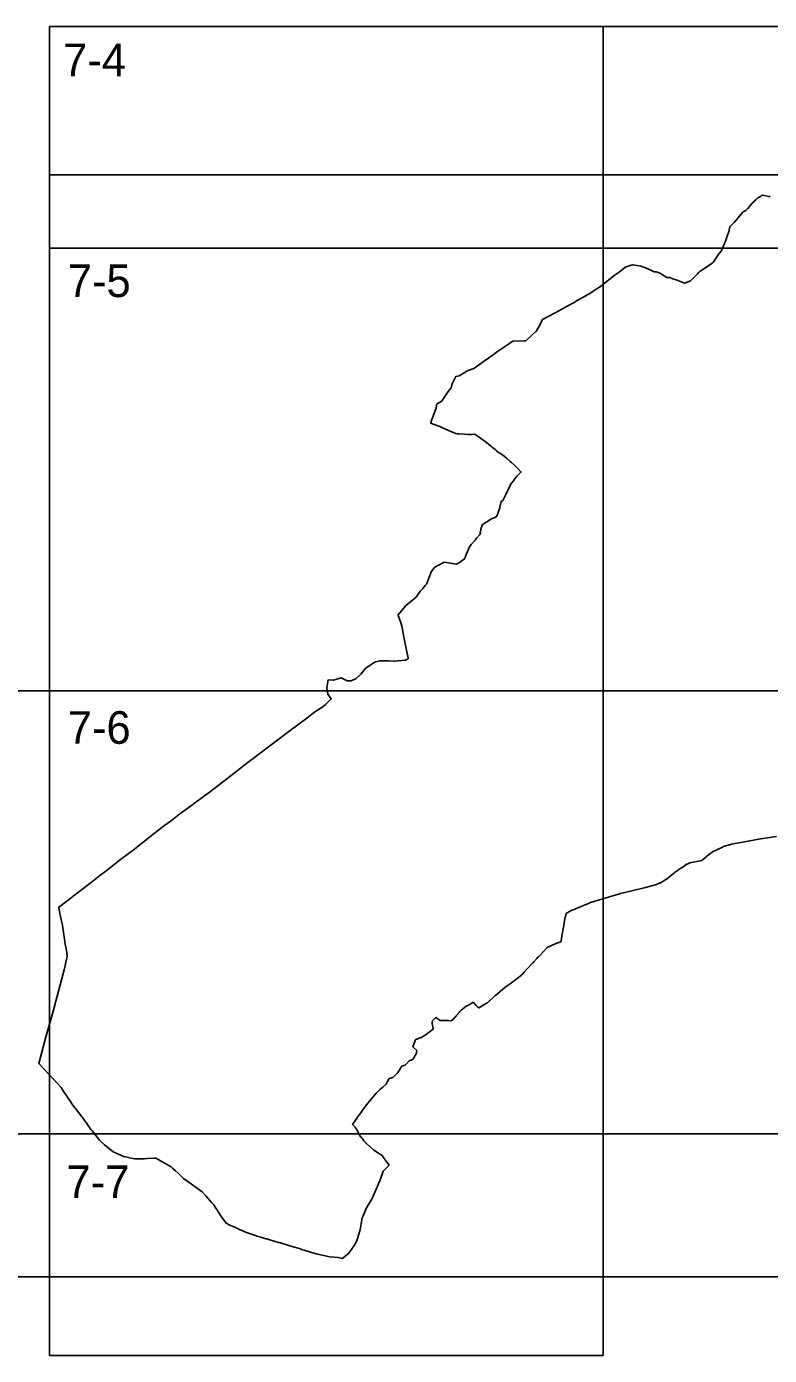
# Model space of a CAD drawing. Extents: x -449577 to -425530, y -1150048 to -1121091.
# Drawn here: x -440104.8 to -439895.1, y -1126653.4 to -1126278.4 of the extents above; entities that cross this region are included whole.
import ezdxf

# ---------------------------------------------------------------- set-up
doc = ezdxf.new("R2010")
doc.units = 0
for name, color, linetype in [('Vrstva 1', 7, 'Continuous'), ('Vrstva 10', 7, 'Continuous'), ('Vrstva 4', 7, 'Continuous')]:
    doc.layers.add(name, color=color, linetype=linetype)

msp = doc.modelspace()

# ---------------------------------------------------------------- linework, layer by layer
at = {"layer": 'Vrstva 1'}
for points in [[(-439894.95, -1126326.41), (-439895.41, -1126326.32), (-439897, -1126326), (-439897.3, -1126326.11), (-439897.86, -1126326.46), (-439898.41, -1126326.78), (-439898.9, -1126327.24), (-439899.43, -1126327.73), (-439899.83, -1126328.12), (-439899.84, -1126328.13), (-439900.17, -1126328.47), (-439900.3, -1126328.61), (-439900.81, -1126329.16), (-439901.26, -1126329.71), (-439901.42, -1126329.9), (-439901.78, -1126330.33), (-439902.52, -1126330.66), (-439902.54, -1126330.66), (-439902.74, -1126330.91), (-439903.6, -1126331.93), (-439903.98, -1126332.38), (-439905.11, -1126333.74), (-439905.12, -1126333.75), (-439906.36, -1126334.92), (-439906.48, -1126335.76), (-439906.53, -1126336.13), (-439906.57, -1126336.23), (-439907.05, -1126337.58), (-439907.49, -1126338.82), (-439907.52, -1126338.9), (-439907.82, -1126339.59), (-439908.75, -1126341.77), (-439908.77, -1126341.78), (-439909.34, -1126342.46), (-439909.64, -1126342.81), (-439909.64, -1126342.82), (-439909.98, -1126343.36), (-439910.85, -1126344.75), (-439910.94, -1126344.89), (-439911.11, -1126345.02), (-439911.64, -1126345.41), (-439912.25, -1126345.86), (-439912.25, -1126345.86), (-439913.22, -1126346.49), (-439913.35, -1126346.58), (-439913.53, -1126346.7), (-439914.83, -1126347.56), (-439914.84, -1126347.57), (-439915.1, -1126347.83), (-439915.22, -1126347.95), (-439915.44, -1126348.18), (-439915.72, -1126348.46), (-439916.29, -1126349.03), (-439917.45, -1126350.19), (-439917.65, -1126350.27), (-439919.15, -1126350.84), (-439921.96, -1126349.72), (-439921.96, -1126349.73), (-439921.97, -1126349.75), (-439922.88, -1126349.37), (-439923.19, -1126349.24), (-439923.21, -1126349.24), (-439923.6, -1126349.24), (-439924.08, -1126349.24), (-439925.64, -1126348.25), (-439925.9, -1126348.12), (-439926.19, -1126347.96), (-439926.25, -1126347.93), (-439926.29, -1126347.91), (-439926.83, -1126347.68), (-439926.88, -1126347.68), (-439926.89, -1126347.68), (-439927.04, -1126347.67), (-439927.16, -1126347.66), (-439927.47, -1126347.64), (-439927.49, -1126347.64), (-439927.49, -1126347.64), (-439927.6, -1126347.6), (-439927.84, -1126347.5), (-439928.44, -1126347.25), (-439928.6, -1126347.18), (-439930.12, -1126346.45), (-439930.74, -1126346.27), (-439931.41, -1126346.07), (-439933.73, -1126345.64), (-439933.74, -1126345.64), (-439934.14, -1126345.75), (-439935.88, -1126346.33), (-439936.01, -1126346.44), (-439937.22, -1126347.4), (-439937.22, -1126347.4), (-439938.37, -1126348.27), (-439938.94, -1126348.7), (-439939.52, -1126349.14), (-439939.68, -1126349.26), (-439941.81, -1126350.9), (-439942.88, -1126351.72), (-439943.35, -1126352.06), (-439944.11, -1126352.57), (-439944.36, -1126352.73), (-439944.95, -1126353.12), (-439944.99, -1126353.15), (-439945.2, -1126353.29), (-439946.11, -1126353.89), (-439946.12, -1126353.89), (-439946.59, -1126354.15), (-439946.74, -1126354.23), (-439946.92, -1126354.33), (-439947.38, -1126354.58), (-439947.56, -1126354.69), (-439947.72, -1126354.78), (-439947.82, -1126354.84), (-439948.06, -1126354.98), (-439949.72, -1126355.92), (-439949.89, -1126356.01), (-439950.12, -1126356.14), (-439952.59, -1126357.54), (-439952.71, -1126357.61), (-439954.82, -1126358.74), (-439955.84, -1126359.29), (-439959.18, -1126361.1), (-439959.35, -1126361.4), (-439959.41, -1126361.51), (-439960.19, -1126362.97), (-439960.87, -1126364.29), (-439961.01, -1126364.42), (-439961.1, -1126364.5), (-439962.24, -1126365.54), (-439963.75, -1126366.92), (-439963.92, -1126367.07), (-439963.92, -1126367.08), (-439964.39, -1126367.09), (-439967.58, -1126367.18), (-439967.59, -1126367.18), (-439968.02, -1126367.47), (-439968.85, -1126368.04), (-439971.32, -1126369.7), (-439971.36, -1126369.72), (-439971.6, -1126369.9), (-439971.87, -1126370.1), (-439974.85, -1126372.23), (-439974.92, -1126372.28), (-439977.92, -1126374.46), (-439978.39, -1126374.8), (-439978.55, -1126374.86), (-439980.49, -1126375.58), (-439980.5, -1126375.58), (-439980.89, -1126375.82), (-439982.77, -1126376.98), (-439983.69, -1126377.19), (-439983.94, -1126377.7), (-439984.7, -1126379.21), (-439984.71, -1126379.22), (-439984.78, -1126379.48), (-439984.98, -1126380.32), (-439985.81, -1126381.43), (-439987.18, -1126383.38), (-439987.74, -1126384.19), (-439987.77, -1126384.21), (-439988.93, -1126384.85), (-439989.03, -1126384.91), (-439989.1, -1126385.3), (-439989.25, -1126386.11), (-439989.3, -1126386.3), (-439990.59, -1126389.88), (-439990.76, -1126390.36), (-439990.73, -1126390.35), (-439990.71, -1126390.34), (-439990.03, -1126390.6), (-439988.22, -1126391.26), (-439987.6, -1126391.55), (-439985.31, -1126392.63), (-439985.29, -1126392.63), (-439984.13, -1126393.1), (-439983.66, -1126393.28), (-439983.63, -1126393.29), (-439983.2, -1126393.32), (-439983.06, -1126393.33), (-439982.84, -1126393.35), (-439981.24, -1126393.45), (-439980.2, -1126393.52), (-439979.15, -1126393.49), (-439978.31, -1126393.46), (-439978.3, -1126393.46), (-439978.02, -1126393.61), (-439977.65, -1126393.87), (-439977.1, -1126394.25), (-439976.71, -1126394.53), (-439975.15, -1126395.67), (-439974.98, -1126395.79), (-439973.87, -1126396.71), (-439973.48, -1126397.03), (-439973.3, -1126397.18), (-439972.55, -1126397.79), (-439972.28, -1126398.02), (-439971.68, -1126398.51), (-439971.46, -1126398.69), (-439970.82, -1126399.11), (-439970.07, -1126399.61), (-439970.04, -1126399.63), (-439969.28, -1126400.31), (-439968.4, -1126401.09), (-439967.96, -1126401.47), (-439966.95, -1126402.36), (-439966.69, -1126402.59), (-439966.64, -1126402.64), (-439966.54, -1126402.74), (-439966.53, -1126402.75), (-439966.44, -1126402.85), (-439966.41, -1126402.88), (-439965.36, -1126404.11), (-439965.37, -1126404.12), (-439965.81, -1126404.61), (-439965.87, -1126404.68), (-439966.44, -1126405.31), (-439967.26, -1126406.37), (-439967.43, -1126406.58), (-439967.99, -1126407.3), (-439968.29, -1126407.83), (-439968.31, -1126407.87), (-439968.32, -1126407.89), (-439968.45, -1126408.17), (-439969.25, -1126409.84), (-439969.56, -1126410.48), (-439970.18, -1126411.77), (-439970.29, -1126412.01), (-439970.3, -1126412.01), (-439970.34, -1126412.04), (-439970.63, -1126412.24), (-439970.71, -1126412.28), (-439970.76, -1126412.38), (-439970.85, -1126412.58), (-439970.94, -1126412.86), (-439971.11, -1126413.42), (-439971.12, -1126413.44), (-439971.24, -1126413.94), (-439971.26, -1126414.01), (-439971.25, -1126414.07), (-439971.24, -1126414.15), (-439971.24, -1126414.22), (-439971.25, -1126414.27), (-439972.13, -1126416.6), (-439972.15, -1126416.65), (-439972.17, -1126416.69), (-439972.18, -1126416.7), (-439972.88, -1126417), (-439973.13, -1126417.11), (-439973.6, -1126417.35), (-439976.21, -1126419.04), (-439976.21, -1126419.04), (-439976.58, -1126420.35), (-439976.66, -1126420.61), (-439976.77, -1126421.03), (-439976.83, -1126421.24), (-439976.83, -1126421.25), (-439976.82, -1126421.25), (-439976.65, -1126421.41), (-439976.66, -1126421.42), (-439977.02, -1126421.81), (-439977.82, -1126422.81), (-439977.83, -1126422.82), (-439978.04, -1126423.07), (-439978.04, -1126423.08), (-439978.16, -1126423.23), (-439979.32, -1126424.58), (-439979.86, -1126425.21), (-439980.62, -1126427.16), (-439981, -1126428.18), (-439981.13, -1126428.53), (-439982.66, -1126429.63), (-439983.28, -1126430.07), (-439983.46, -1126430.11), (-439983.48, -1126430.11), (-439984.11, -1126430.02), (-439986.95, -1126429.6), (-439987.44, -1126429.84), (-439988.77, -1126430.48), (-439989.31, -1126430.74), (-439989.34, -1126430.77), (-439989.77, -1126431.18), (-439989.94, -1126431.4), (-439990.6, -1126432.25), (-439990.6, -1126432.26), (-439991.27, -1126434.06), (-439991.84, -1126435.56), (-439991.84, -1126435.56), (-439991.98, -1126435.78), (-439992.31, -1126436.15), (-439993.03, -1126436.95), (-439993.73, -1126437.72), (-439993.74, -1126437.74), (-439993.87, -1126437.93), (-439994.94, -1126439.5), (-439995.41, -1126439.88), (-439996.98, -1126441.14), (-439997.65, -1126441.68), (-439997.75, -1126441.76), (-439997.78, -1126441.8), (-439998.9, -1126443.23), (-440000.04, -1126444.54), (-439999.89, -1126444.71), (-439999.88, -1126444.74), (-439999.88, -1126444.75), (-439998.87, -1126447.51), (-439998.59, -1126449.17), (-439998.27, -1126451.12), (-439997.86, -1126453.08), (-439997.13, -1126456.58), (-439997.09, -1126456.78), (-439997.74, -1126457.12), (-439997.86, -1126457.19), (-440001.03, -1126457.45), (-440001.19, -1126457.45), (-440002.68, -1126457.42), (-440005.07, -1126457.4), (-440006.35, -1126457.67), (-440006.95, -1126457.94), (-440007.93, -1126458.74), (-440009.23, -1126459.61), (-440009.32, -1126459.72), (-440010.48, -1126461.14), (-440011.93, -1126462.48), (-440012.62, -1126462.8), (-440013.22, -1126463.08), (-440014.39, -1126463.01), (-440016, -1126462.16), (-440018.24, -1126462.83), (-440019.72, -1126462.8), (-440020.1, -1126464.91), (-440020.11, -1126464.93), (-440020.12, -1126465.02), (-440019.83, -1126466.83), (-440018.86, -1126468.15), (-440018.85, -1126468.17), (-440019.59, -1126468.92), (-440020.2, -1126469.48), (-440020.45, -1126469.71), (-440021.25, -1126470.34), (-440023.18, -1126471.57), (-440023.24, -1126471.61), (-440025.21, -1126473.14), (-440025.27, -1126473.18), (-440025.76, -1126473.56), (-440030.42, -1126477.02), (-440030.45, -1126477.05), (-440035.4, -1126480.81), (-440039.66, -1126484.06), (-440040.54, -1126484.72), (-440043.11, -1126486.66), (-440047.11, -1126489.79), (-440049.55, -1126491.66), (-440052.86, -1126494.19), (-440052.91, -1126494.23), (-440057.7, -1126497.74), (-440057.93, -1126497.92), (-440061.54, -1126500.6), (-440063.93, -1126502.42), (-440065.9, -1126503.9), (-440068.22, -1126505.65), (-440068.45, -1126505.82), (-440069.58, -1126506.71), (-440074.4, -1126510.51), (-440078.29, -1126513.46), (-440082.51, -1126516.71), (-440083.8, -1126517.71), (-440086.19, -1126519.59), (-440087.37, -1126520.51), (-440091.31, -1126523.56), (-440092.24, -1126524.27), (-440093.48, -1126525.23), (-440095.8, -1126527.03), (-440095.8, -1126527.03), (-440095.76, -1126527.21), (-440095.47, -1126528.59), (-440095.44, -1126528.75), (-440094.91, -1126531.29), (-440094.75, -1126532.02), (-440094.75, -1126532.06), (-440093.82, -1126537.94), (-440093.81, -1126537.97), (-440093.51, -1126539.7), (-440093.51, -1126539.72), (-440093.45, -1126540.09), (-440093.39, -1126540.51), (-440093.42, -1126540.88), (-440093.57, -1126541.61), (-440093.95, -1126543.4), (-440094.24, -1126544.58), (-440094.26, -1126544.63), (-440095.37, -1126548.8), (-440097.47, -1126556.68), (-440099.46, -1126563.9), (-440101.39, -1126571), (-440101.4, -1126571.04), (-440096.12, -1126576.64), (-440095.07, -1126577.77), (-440094.31, -1126578.99), (-440092.29, -1126582.05), (-440092.24, -1126582.12), (-440091.23, -1126583.53), (-440091.07, -1126583.74), (-440089.19, -1126586.22), (-440088.62, -1126586.96), (-440088.59, -1126587), (-440088.07, -1126587.72), (-440086.69, -1126589.62), (-440086.36, -1126590.07), (-440084.21, -1126592.79), (-440082.81, -1126594.01), (-440080.41, -1126595.99), (-440078.67, -1126596.74), (-440077.48, -1126597.26), (-440077.35, -1126597.31), (-440076.02, -1126597.59), (-440075.88, -1126597.62), (-440074.26, -1126597.95), (-440074.23, -1126597.95), (-440073.27, -1126597.93), (-440072.89, -1126597.93), (-440072.37, -1126597.92), (-440071.69, -1126597.91), (-440070.78, -1126597.87), (-440068.83, -1126597.71), (-440068.38, -1126597.78), (-440067.72, -1126598.13), (-440066, -1126599.08), (-440064.04, -1126600.18), (-440063.52, -1126600.66), (-440062.8, -1126601.34), (-440062, -1126602.09), (-440060.68, -1126603.39), (-440060.54, -1126603.49), (-440059.35, -1126604.34), (-440056.94, -1126606.05), (-440055.3, -1126607.23), (-440054.25, -1126608.41), (-440052.61, -1126610.23), (-440051.97, -1126610.94), (-440051.61, -1126611.53), (-440051.15, -1126612.27), (-440050.21, -1126613.74), (-440049.58, -1126614.66), (-440048.54, -1126616.1), (-440047.47, -1126616.61), (-440046.09, -1126617.26), (-440044.78, -1126617.87), (-440042.81, -1126618.76), (-440041.68, -1126619.11), (-440039.96, -1126619.68), (-440039.81, -1126619.73), (-440038.72, -1126620.05), (-440037.3, -1126620.47), (-440037.29, -1126620.47), (-440037.08, -1126620.53), (-440037.02, -1126620.55), (-440036.16, -1126620.81), (-440033.77, -1126621.5), (-440033.65, -1126621.54), (-440033.17, -1126621.68), (-440030.24, -1126622.55), (-440027.55, -1126623.38), (-440027.21, -1126623.48), (-440026.45, -1126623.71), (-440024.44, -1126624.33), (-440022.71, -1126624.88), (-440019.25, -1126625.62)], [(-440019.25, -1126625.62), (-440016.86, -1126625.81), (-440015.66, -1126626.04), (-440015.55, -1126625.95), (-440013.97, -1126624.68), (-440012.94, -1126623.2), (-440012.83, -1126623.05), (-440012.31, -1126622.29), (-440012.2, -1126622.12), (-440012.06, -1126621.89), (-440011.68, -1126621.26), (-440011.41, -1126620.43), (-440011.39, -1126620.36), (-440011.37, -1126620.31), (-440011.34, -1126620.2), (-440011.31, -1126620.11), (-440011.31, -1126620.1), (-440010.68, -1126617.9), (-440010.54, -1126617.38), (-440010.09, -1126614.63), (-440010.09, -1126614.63), (-440009.9, -1126614.19), (-440009.64, -1126613.57), (-440008.85, -1126611.74), (-440007.28, -1126609.09), (-440005.53, -1126604.96), (-440005.21, -1126604.32), (-440005.17, -1126604.19), (-440004.78, -1126603.09), (-440004.19, -1126601.42), (-440002.51, -1126599.71), (-440003.44, -1126598.47), (-440003.5, -1126598.38), (-440003.55, -1126598.32), (-440003.58, -1126598.28), (-440003.65, -1126598.18), (-440003.7, -1126598.1), (-440003.78, -1126597.98), (-440004.14, -1126597.46), (-440004.51, -1126597), (-440005.08, -1126596.63), (-440005.18, -1126596.57), (-440006.83, -1126595.5), (-440009.02, -1126593.56), (-440009.15, -1126593.39), (-440009.18, -1126593.35), (-440009.26, -1126593.25), (-440009.6, -1126592.83), (-440009.93, -1126592.42), (-440010.19, -1126592.1), (-440010.67, -1126591.51), (-440010.75, -1126591.41), (-440011.25, -1126590.45), (-440011.54, -1126589.89), (-440011.77, -1126589.46), (-440011.82, -1126589.37), (-440011.86, -1126589.32), (-440012.12, -1126589.03), (-440012.32, -1126588.8), (-440012.58, -1126588.51), (-440012.8, -1126588.26), (-440010.94, -1126585.52), (-440010.85, -1126585.4), (-440010.53, -1126584.95), (-440010.21, -1126584.51), (-440008.88, -1126582.68), (-440006.2, -1126579.42), (-440005.85, -1126579.1), (-440005.14, -1126578.4), (-440005.03, -1126578.31), (-440004.84, -1126578.17), (-440004.24, -1126577.69), (-440003.38, -1126576.85), (-440002.97, -1126576.09), (-440002.5, -1126575.22), (-440001.45, -1126574.98), (-440000.05, -1126573.55), (-439999.51, -1126572.7), (-439999.5, -1126572.69), (-439999.5, -1126572.67), (-439999.29, -1126572.34), (-439999.24, -1126572.26), (-439999, -1126571.87), (-439997.84, -1126571.43), (-439996.82, -1126570.25), (-439996.29, -1126570.05), (-439996.17, -1126570), (-439995.75, -1126569.84), (-439995.53, -1126569.45), (-439995.48, -1126569.36), (-439995.31, -1126569.06), (-439994.9, -1126568.32), (-439994.7, -1126567.41), (-439994.7, -1126567.39), (-439994.69, -1126567.38), (-439995.74, -1126566.39), (-439995.76, -1126566.38), (-439995.77, -1126566.36), (-439995.82, -1126566.32), (-439995.17, -1126564.52), (-439995.1, -1126564.32), (-439994.94, -1126564.26), (-439994.21, -1126563.97), (-439993.52, -1126563.7), (-439993.4, -1126563.65), (-439992.19, -1126562.94), (-439992.07, -1126562.86), (-439992.07, -1126562.86), (-439992.06, -1126562.85), (-439991.94, -1126562.78), (-439990.08, -1126561.38), (-439990.08, -1126561.34), (-439990.11, -1126561.18), (-439990.18, -1126560.7), (-439990.24, -1126560.35), (-439990.34, -1126559.73), (-439990.36, -1126559.62), (-439990.38, -1126559.49), (-439990.4, -1126559.32), (-439990.43, -1126559.18), (-439989.89, -1126558.62), (-439989.33, -1126558.05), (-439989.29, -1126558), (-439989.15, -1126558.1), (-439988.15, -1126558.89), (-439987.47, -1126558.9), (-439987.41, -1126558.9), (-439987.16, -1126558.91), (-439987, -1126558.91), (-439985.69, -1126558.93), (-439985.06, -1126558.95), (-439984.79, -1126558.79), (-439984.76, -1126558.77), (-439984.64, -1126558.7), (-439984.5, -1126558.61), (-439984.46, -1126558.58), (-439983.92, -1126557.98), (-439983.81, -1126557.86), (-439983.72, -1126557.76), (-439983.55, -1126557.58), (-439983.47, -1126557.49), (-439983.36, -1126557.37), (-439983.33, -1126557.33), (-439983.3, -1126557.3), (-439983.25, -1126557.24), (-439983.16, -1126557.13), (-439982.76, -1126556.63), (-439982.55, -1126556.37), (-439982.3, -1126556.05), (-439982.19, -1126555.97), (-439980.73, -1126554.9), (-439980.52, -1126554.77), (-439979.16, -1126554), (-439978.76, -1126553.77), (-439978.76, -1126553.77), (-439978.62, -1126553.92), (-439977.91, -1126554.63), (-439977.54, -1126555.01), (-439977.36, -1126555.18), (-439977.21, -1126555.33), (-439977.12, -1126555.29), (-439975.84, -1126554.52), (-439975.75, -1126554.47), (-439974.82, -1126553.91), (-439974.78, -1126553.88), (-439974.45, -1126553.59), (-439974.4, -1126553.55), (-439974.23, -1126553.4), (-439974.22, -1126553.39), (-439974.22, -1126553.39), (-439974.18, -1126553.35), (-439974.14, -1126553.31), (-439973.25, -1126552.5), (-439973.23, -1126552.49), (-439972.64, -1126551.95), (-439972.53, -1126551.86), (-439972.42, -1126551.76), (-439972.42, -1126551.76), (-439972.41, -1126551.76), (-439972.41, -1126551.76), (-439972.41, -1126551.75), (-439972.4, -1126551.75), (-439972.39, -1126551.74), (-439972.39, -1126551.74), (-439972.38, -1126551.73), (-439972.38, -1126551.73), (-439972.37, -1126551.73), (-439972.37, -1126551.73), (-439971.79, -1126551.24), (-439969.8, -1126549.56), (-439968.6, -1126548.71), (-439968.48, -1126548.63), (-439968.43, -1126548.59), (-439968.41, -1126548.58), (-439968.36, -1126548.55), (-439968, -1126548.28), (-439966.76, -1126547.34), (-439966.58, -1126547.2), (-439966.37, -1126547.04), (-439966.35, -1126547.02), (-439965.47, -1126546.35), (-439965.12, -1126546.08), (-439965.07, -1126546.02), (-439964.98, -1126545.92), (-439964.34, -1126545.24), (-439963.44, -1126544.26), (-439962.08, -1126542.85), (-439961.86, -1126542.62), (-439961.61, -1126542.34), (-439960.77, -1126541.39), (-439960.48, -1126541.07), (-439960.28, -1126540.86), (-439959.99, -1126540.54), (-439958.81, -1126539.35), (-439957.88, -1126538.33), (-439955.82, -1126537.32), (-439955.66, -1126537.27), (-439955.46, -1126537.19), (-439954.02, -1126536.7), (-439953.87, -1126535.83), (-439953.71, -1126534.96), (-439953.29, -1126532.59), (-439953.21, -1126532.12), (-439952.88, -1126530.24), (-439952.68, -1126529.36), (-439952.65, -1126529.24), (-439952.6, -1126529.05), (-439952.59, -1126529.01), (-439952.57, -1126528.94), (-439952.56, -1126528.9), (-439952.55, -1126528.85), (-439952.54, -1126528.81), (-439952.53, -1126528.79), (-439952.47, -1126528.58), (-439951.39, -1126528.04), (-439951.1, -1126527.9), (-439951.08, -1126527.89), (-439950.83, -1126527.76), (-439950.78, -1126527.74), (-439949.01, -1126527.02), (-439948.98, -1126527.01), (-439948.95, -1126526.99), (-439948.15, -1126526.68), (-439947.19, -1126526.28), (-439946.38, -1126525.94), (-439945.44, -1126525.55), (-439945.36, -1126525.52), (-439944.75, -1126525.28), (-439944.9, -1126525.44), (-439944.66, -1126525.35), (-439944.17, -1126525.15), (-439943.64, -1126524.99), (-439941.94, -1126524.47), (-439941.35, -1126524.3), (-439940.9, -1126524.18), (-439940.01, -1126523.93), (-439938.7, -1126523.55), (-439937.16, -1126523.09), (-439933.62, -1126522.22), (-439930.85, -1126521.55), (-439930.18, -1126521.34), (-439928.69, -1126520.98), (-439928.48, -1126520.92), (-439927.05, -1126520.53), (-439926.45, -1126520.27), (-439926.23, -1126520.17), (-439926.07, -1126520.11), (-439925.25, -1126519.66), (-439925.19, -1126519.62), (-439923.88, -1126518.84), (-439922.73, -1126517.79), (-439922.08, -1126517.29), (-439921.95, -1126517.18), (-439921.93, -1126517.17), (-439921.77, -1126517.04), (-439921.62, -1126516.94), (-439920.82, -1126516.38), (-439920.76, -1126516.34), (-439920.69, -1126516.29), (-439920.18, -1126515.94), (-439919.81, -1126515.68), (-439919.15, -1126515.22), (-439918.56, -1126514.81), (-439918.4, -1126514.84), (-439918.39, -1126514.84), (-439918.37, -1126514.82), (-439917.64, -1126514.43), (-439914.68, -1126513.85), (-439914.26, -1126513.7), (-439912.23, -1126512.07), (-439911.76, -1126511.73), (-439911.73, -1126511.71), (-439911.37, -1126511.45), (-439911.19, -1126511.33), (-439909.8, -1126510.63), (-439908.39, -1126509.99), (-439908.09, -1126509.84), (-439906.83, -1126509.38), (-439905.83, -1126509.13), (-439900.12, -1126508.07), (-439898.7, -1126507.81), (-439896.99, -1126507.56), (-439893.12, -1126506.99)]]:
    msp.add_lwpolyline(points, dxfattribs=at)
at = {"layer": 'Vrstva 10'}
msp.add_lwpolyline([(-439785.86, -1126320.23), (-439785.86, -1126631.21), (-440118.73, -1126631.21), (-440118.73, -1126465.91), (-440098.36, -1126465.91), (-440098.36, -1126340.91), (-440098.36, -1126320.23), (-439785.86, -1126320.23)], dxfattribs=at)
at = {"layer": 'Vrstva 4'}
for p, q in [((-440098.36, -1126278.41), (-439785.86, -1126278.41)), ((-440098.36, -1126653.41), (-439942.11, -1126653.41))]:
    msp.add_line(p, q, dxfattribs=at)
for points in [[(-439942.11, -1126278.41), (-439942.11, -1126340.91), (-440098.36, -1126340.91), (-440098.36, -1126278.41)], [(-439785.86, -1126278.41), (-439785.86, -1126340.91), (-439942.11, -1126340.91), (-439942.11, -1126278.41)], [(-440176.49, -1126465.91), (-440098.36, -1126465.91), (-440098.36, -1126590.91), (-440176.49, -1126590.91)], [(-440098.36, -1126653.41), (-440098.36, -1126590.91), (-439942.11, -1126590.91), (-439942.11, -1126653.41)]]:
    msp.add_lwpolyline(points, dxfattribs=at)
for points in [[(-439942.11, -1126340.91), (-439942.11, -1126465.91), (-440098.36, -1126465.91), (-440098.36, -1126340.91)], [(-439785.86, -1126340.91), (-439785.86, -1126465.91), (-439942.11, -1126465.91), (-439942.11, -1126340.91)], [(-439942.11, -1126465.91), (-439942.11, -1126590.91), (-440098.36, -1126590.91), (-440098.36, -1126465.91)], [(-439785.86, -1126465.91), (-439785.86, -1126590.91), (-439942.11, -1126590.91), (-439942.11, -1126465.91)]]:
    msp.add_lwpolyline(points, close=True, dxfattribs=at)

# ---------------------------------------------------------------- texts
at = {"layer": 'Vrstva 1'}
for s, p in [('7-4', (-440094.55, -1126292.41)), ('7-5', (-440093.24, -1126354.75)), ('7-6', (-440093.24, -1126480.82)), ('7-7', (-440093.6, -1126608.99))]:
    msp.add_text(s, height=9.2, dxfattribs=at).set_placement(p)

doc.saveas('drawing.dxf')
